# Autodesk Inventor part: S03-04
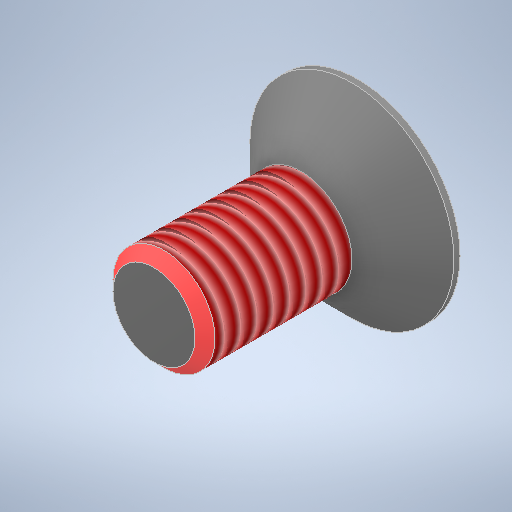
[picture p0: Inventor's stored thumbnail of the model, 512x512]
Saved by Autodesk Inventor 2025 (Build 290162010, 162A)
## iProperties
Manager: DIN 7991
Created: 2025-04
Part Number: S03-04
Material: Všeobecné
Document SubType Name: Modeling
Designer: Patrik
Density: 1 g/cm^3
Appearance: Výchozí
Description: Šroub se zápustnou hlavou a vnitřním šestihranem
Stock Number: E 1220/5x10
Mass: 0.259782 g
Surface Area: 3.23082 cm^2
Volume: 0.259782 cm^3
User Status: 10.9
Author: Patrik
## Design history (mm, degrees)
feature "Base1"
feature "Závit1" dims "d0" = 6.71, "d1" = 0
node "Těleso1"
